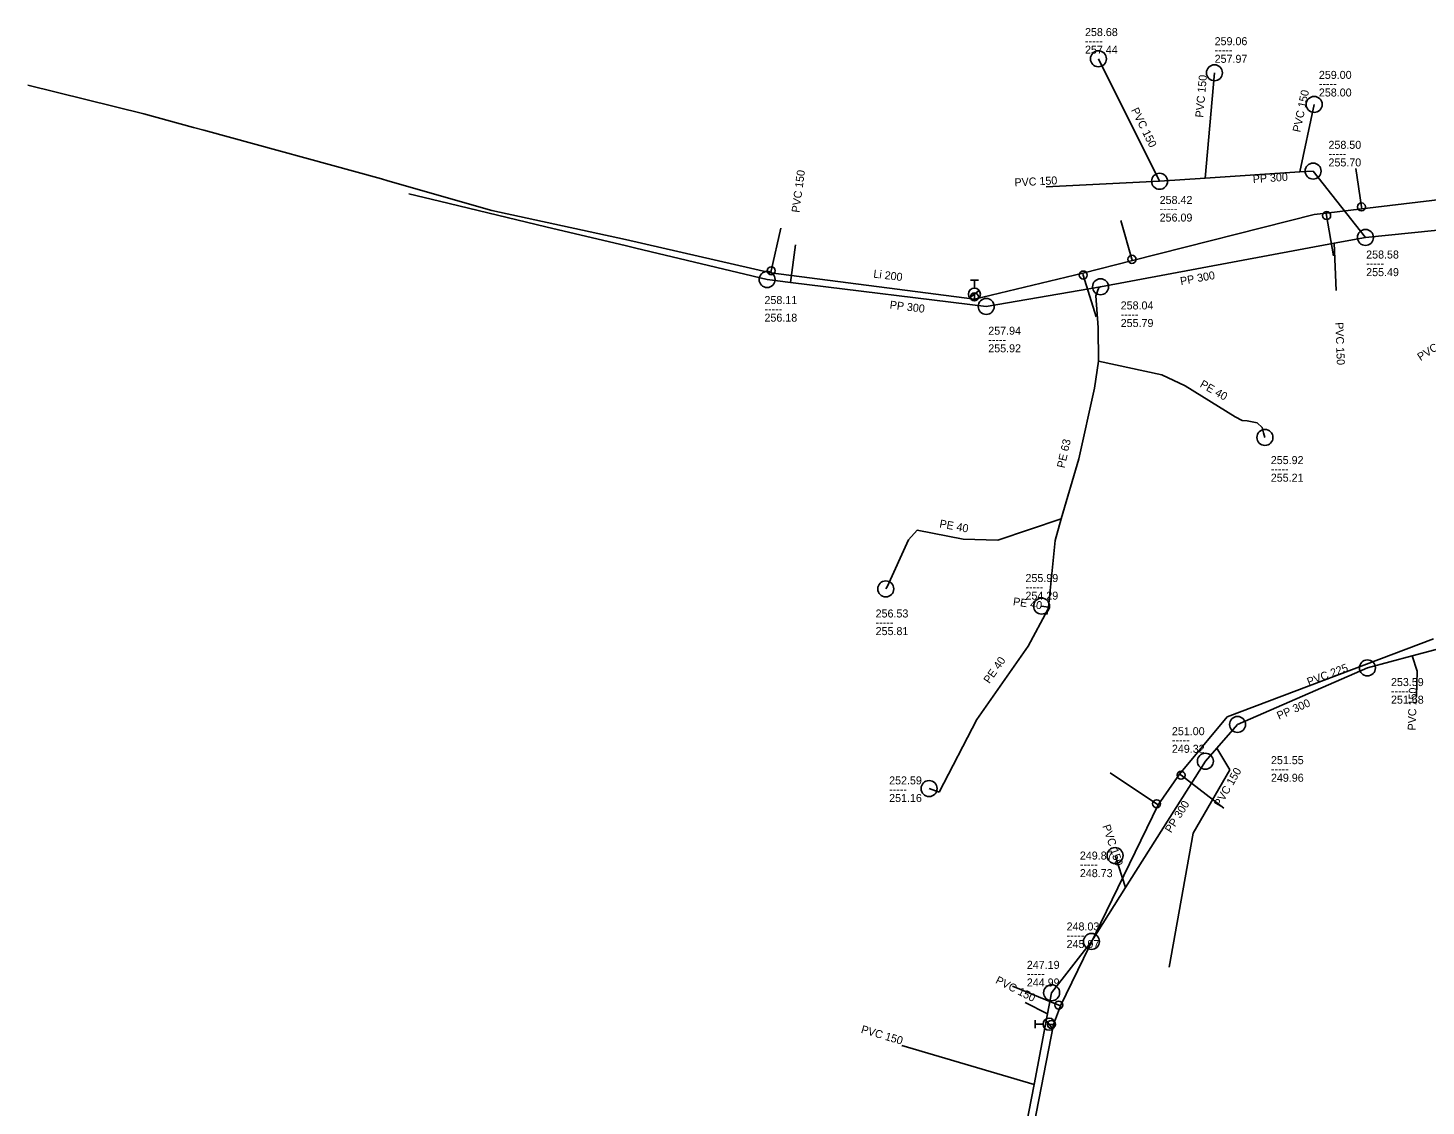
# Model space of a CAD drawing. Extents: x -770828 to -770111, y -1050344 to -1049447.
# Drawn here: x -770827.7 to -770653, y -1050061.2 to -1049926.5 of the extents above; entities that cross this region are included whole.
import ezdxf

# ---------------------------------------------------------------- set-up
doc = ezdxf.new("R2010")
doc.units = 0
doc.layers.add('Level 0', color=7, linetype='Continuous')

msp = doc.modelspace()

# ---------------------------------------------------------------- linework, layer by layer
at = {"layer": 'Level 0'}
for p, q in [((-770686.27, -1049945.68), (-770693.92, -1049930.37)), ((-770680.57, -1049945.3), (-770679.41, -1049932.12)), ((-770827.7, -1049933.66), (-770813.22, -1049937.25)), ((-770813.22, -1049937.25), (-770807.01, -1049938.95)), ((-770668.75, -1049944.51), (-770666.95, -1049936.07)), ((-770807.01, -1049938.95), (-770805.73, -1049939.3)), ((-770805.73, -1049939.3), (-770783.52, -1049945.37)), ((-770680.57, -1049945.3), (-770668.75, -1049944.51)), ((-770668.75, -1049944.51), (-770667.08, -1049944.4)), ((-770667.08, -1049944.4), (-770660.54, -1049952.69)), ((-770661.04, -1049948.87), (-770661.73, -1049944.09)), ((-770783.52, -1049945.37), (-770782.73, -1049945.6)), ((-770782.73, -1049945.6), (-770769.73, -1049949.34)), ((-770700.43, -1049946.39), (-770686.27, -1049945.68)), ((-770686.27, -1049945.68), (-770680.57, -1049945.3)), ((-770780.08, -1049947.26), (-770776.28, -1049948.17)), ((-770661, -1049949.12), (-770650.48, -1049947.87)), ((-770776.28, -1049948.17), (-770762.96, -1049951.35)), ((-770769.73, -1049949.34), (-770753.04, -1049952.96)), ((-770689.67, -1049955.59), (-770666.94, -1049949.83)), ((-770666.94, -1049949.83), (-770665.44, -1049949.65)), ((-770665.44, -1049949.65), (-770661, -1049949.12)), ((-770665.44, -1049949.65), (-770665.39, -1049949.97)), ((-770661, -1049949.12), (-770661.04, -1049948.87)), ((-770762.96, -1049951.35), (-770752.89, -1049953.75)), ((-770734.8, -1049956.86), (-770733.62, -1049951.55)), ((-770689.72, -1049955.43), (-770691.12, -1049950.59)), ((-770665.39, -1049949.97), (-770664.55, -1049955.01)), ((-770660.54, -1049952.69), (-770648.08, -1049951.45)), ((-770753.04, -1049952.96), (-770734.86, -1049957.12)), ((-770664.43, -1049953.41), (-770660.54, -1049952.69)), ((-770752.89, -1049953.75), (-770751.73, -1049954.03)), ((-770751.73, -1049954.03), (-770735.32, -1049957.95)), ((-770732.39, -1049958.31), (-770731.76, -1049953.63)), ((-770693.65, -1049958.86), (-770664.43, -1049953.41)), ((-770664.21, -1049959.33), (-770664.43, -1049953.41)), ((-770695.88, -1049957.16), (-770689.67, -1049955.59)), ((-770689.67, -1049955.59), (-770689.72, -1049955.43)), ((-770735.32, -1049957.95), (-770732.39, -1049958.31)), ((-770734.86, -1049957.12), (-770734.8, -1049956.86)), ((-770734.86, -1049957.12), (-770709.39, -1049960.4)), ((-770732.39, -1049958.31), (-770707.93, -1049961.32)), ((-770709.92, -1049958.02), (-770708.92, -1049958.02)), ((-770709.42, -1049959.02), (-770709.42, -1049958.02)), ((-770709.39, -1049960.4), (-770695.88, -1049957.16)), ((-770695.88, -1049957.16), (-770695.81, -1049957.39)), ((-770695.81, -1049957.39), (-770694.21, -1049962.61)), ((-770710.01, -1049960.23), (-770708.83, -1049959.31)), ((-770709.42, -1049959.77), (-770709.42, -1049960.13)), ((-770709.42, -1049960.13), (-770709.39, -1049960.4)), ((-770707.93, -1049961.32), (-770693.65, -1049958.86)), ((-770694.22, -1049959.98), (-770693.86, -1049958.95)), ((-770693.94, -1049963.95), (-770694.22, -1049959.98)), ((-770693.86, -1049958.95), (-770693.65, -1049958.86)), ((-770693.92, -1049968.17), (-770693.94, -1049963.95)), ((-770694.4, -1049971.53), (-770693.92, -1049968.17)), ((-770693.92, -1049968.17), (-770686, -1049969.86)), ((-770686, -1049969.86), (-770683.06, -1049971.22)), ((-770696.37, -1049980.37), (-770694.4, -1049971.53)), ((-770683.06, -1049971.22), (-770676.81, -1049975.12)), ((-770676.81, -1049975.12), (-770675.95, -1049975.56)), ((-770675.95, -1049975.56), (-770675.34, -1049975.63)), ((-770675.34, -1049975.63), (-770674.07, -1049975.87)), ((-770674.07, -1049975.87), (-770673.46, -1049976.46)), ((-770673.46, -1049976.46), (-770673.29, -1049977.12)), ((-770673.29, -1049977.12), (-770673.1, -1049977.69)), ((-770698.56, -1049987.85), (-770696.37, -1049980.37)), ((-770698.56, -1049987.85), (-770706.48, -1049990.52)), ((-770699.3, -1049990.55), (-770698.56, -1049987.85)), ((-770716.55, -1049989.29), (-770717.66, -1049990.48)), ((-770710.81, -1049990.4), (-770716.55, -1049989.29)), ((-770717.66, -1049990.48), (-770720.33, -1049996.37)), ((-770706.48, -1049990.52), (-770710.81, -1049990.4)), ((-770700.15, -1049998.9), (-770699.3, -1049990.55)), ((-770720.33, -1049996.37), (-770720.49, -1049996.62)), ((-770700.25, -1049999.18), (-770702.71, -1050003.76)), ((-770701.02, -1049998.77), (-770700.15, -1049998.9)), ((-770700.35, -1049999.81), (-770700.25, -1049999.18)), ((-770700.25, -1049999.18), (-770700.15, -1049998.9)), ((-770642.7, -1050001.79), (-770654.72, -1050005)), ((-770702.71, -1050003.76), (-770709.12, -1050012.92)), ((-770677.84, -1050012.6), (-770652.02, -1050002.86)), ((-770654.72, -1050005), (-770660.3, -1050006.49)), ((-770654.72, -1050005), (-770654.07, -1050006.89)), ((-770660.3, -1050006.49), (-770676.53, -1050013.56)), ((-770654.07, -1050006.89), (-770654.16, -1050010.06)), ((-770683.78, -1050019.75), (-770677.84, -1050012.6)), ((-770709.12, -1050012.92), (-770713.8, -1050022)), ((-770676.53, -1050013.56), (-770679.12, -1050016.52)), ((-770679.12, -1050016.52), (-770680.55, -1050018.15)), ((-770679.12, -1050016.52), (-770677.48, -1050019.23)), ((-770686.64, -1050023.47), (-770692.43, -1050019.6)), ((-770680.55, -1050018.15), (-770690.52, -1050033.93)), ((-770677.48, -1050019.23), (-770682.09, -1050027.16)), ((-770686.45, -1050023.6), (-770683.78, -1050019.75)), ((-770683.78, -1050019.75), (-770683.59, -1050019.9)), ((-770683.59, -1050019.9), (-770678.25, -1050024)), ((-770713.8, -1050022), (-770715.08, -1050021.57)), ((-770698.66, -1050048.72), (-770686.45, -1050023.6)), ((-770686.45, -1050023.6), (-770686.64, -1050023.47)), ((-770682.09, -1050027.16), (-770685.08, -1050043.91)), ((-770690.52, -1050033.93), (-770691.84, -1050029.94)), ((-770690.52, -1050033.93), (-770694.79, -1050040.68)), ((-770694.79, -1050040.68), (-770699.76, -1050047.09)), ((-770698.88, -1050048.63), (-770704.64, -1050046.25)), ((-770699.76, -1050047.09), (-770700.26, -1050049.71)), ((-770700.26, -1050049.71), (-770703.05, -1050048.29)), ((-770699.54, -1050051.07), (-770698.66, -1050048.72)), ((-770698.66, -1050048.72), (-770698.88, -1050048.63)), ((-770702.51, -1050066.39), (-770699.54, -1050051.07)), ((-770700.26, -1050049.71), (-770701.96, -1050058.56)), ((-770701.84, -1050051.51), (-770701.84, -1050050.51)), ((-770700.84, -1050051.01), (-770701.84, -1050051.01)), ((-770699.63, -1050051.6), (-770700.55, -1050050.42)), ((-770699.79, -1050051.05), (-770700.09, -1050051.01)), ((-770699.54, -1050051.07), (-770699.79, -1050051.05)), ((-770701.96, -1050058.56), (-770718.5, -1050053.69)), ((-770701.96, -1050058.56), (-770703.34, -1050065.74))]:
    msp.add_line(p, q, dxfattribs=at)
for centre, radius in [((-770693.92, -1049930.37), 1), ((-770679.41, -1049932.12), 1), ((-770666.95, -1049936.07), 1), ((-770667.08, -1049944.4), 1), ((-770686.27, -1049945.68), 1), ((-770665.39, -1049949.97), 0.5), ((-770661.04, -1049948.87), 0.5), ((-770660.54, -1049952.69), 1), ((-770689.72, -1049955.43), 0.5), ((-770734.8, -1049956.86), 0.5), ((-770735.32, -1049957.95), 1), ((-770695.81, -1049957.39), 0.5), ((-770693.65, -1049958.86), 1), ((-770709.42, -1049959.77), 0.75), ((-770709.42, -1049960.13), 0.5), ((-770707.93, -1049961.32), 1), ((-770673.1, -1049977.69), 1), ((-770720.49, -1049996.62), 1), ((-770701.02, -1049998.77), 1), ((-770660.3, -1050006.49), 1), ((-770676.53, -1050013.56), 1), ((-770680.55, -1050018.15), 1), ((-770683.59, -1050019.9), 0.5), ((-770715.08, -1050021.57), 1), ((-770686.64, -1050023.47), 0.5), ((-770691.84, -1050029.94), 1), ((-770694.79, -1050040.68), 1), ((-770699.76, -1050047.09), 1), ((-770698.88, -1050048.63), 0.5), ((-770700.09, -1050051.01), 0.75), ((-770699.79, -1050051.05), 0.5)]:
    msp.add_circle(centre, radius, dxfattribs=at)

# ---------------------------------------------------------------- texts
for s, p in [('258.68', (-770695.59, -1049927.53)), ('-----', (-770695.59, -1049928.63)), ('257.44', (-770695.59, -1049929.73)), ('259.06', (-770679.39, -1049928.67)), ('-----', (-770679.39, -1049929.77)), ('257.97', (-770679.39, -1049930.87)), ('259.00', (-770666.36, -1049932.88)), ('-----', (-770666.36, -1049933.98)), ('258.00', (-770666.36, -1049935.08)), ('258.50', (-770665.16, -1049941.62)), ('-----', (-770665.16, -1049942.72)), ('255.70', (-770665.16, -1049943.82)), ('258.42', (-770686.26, -1049948.51)), ('-----', (-770686.26, -1049949.61)), ('256.09', (-770686.26, -1049950.71)), ('258.58', (-770660.45, -1049955.33)), ('-----', (-770660.45, -1049956.43)), ('255.49', (-770660.45, -1049957.53)), ('258.11', (-770735.65, -1049961.02)), ('-----', (-770735.65, -1049962.12)), ('258.04', (-770691.13, -1049961.69)), ('256.18', (-770735.65, -1049963.22)), ('-----', (-770691.13, -1049962.79)), ('255.79', (-770691.13, -1049963.89)), ('-----', (-770707.68, -1049965.95)), ('257.94', (-770707.68, -1049964.85)), ('255.92', (-770707.68, -1049967.05)), ('255.92', (-770672.37, -1049981.02)), ('-----', (-770672.37, -1049982.12)), ('255.21', (-770672.37, -1049983.22)), ('255.99', (-770703.03, -1049995.76)), ('-----', (-770703.03, -1049996.86)), ('254.29', (-770703.03, -1049997.96)), ('256.53', (-770721.76, -1050000.19)), ('-----', (-770721.76, -1050001.29)), ('255.81', (-770721.76, -1050002.39)), ('253.59', (-770657.35, -1050008.76)), ('-----', (-770657.35, -1050009.86)), ('251.68', (-770657.35, -1050010.96)), ('251.00', (-770684.73, -1050014.9)), ('-----', (-770684.73, -1050016)), ('249.32', (-770684.73, -1050017.1)), ('251.55', (-770672.35, -1050018.52)), ('-----', (-770672.35, -1050019.62)), ('249.96', (-770672.35, -1050020.72)), ('252.59', (-770720.07, -1050021.05)), ('-----', (-770720.07, -1050022.15)), ('251.16', (-770720.07, -1050023.25)), ('249.87', (-770696.23, -1050030.44)), ('-----', (-770696.23, -1050031.54)), ('248.73', (-770696.23, -1050032.64)), ('248.03', (-770697.89, -1050039.3)), ('-----', (-770697.89, -1050040.4)), ('245.97', (-770697.89, -1050041.5)), ('247.19', (-770702.86, -1050044.1)), ('-----', (-770702.86, -1050045.2)), ('244.99', (-770702.86, -1050046.3))]:
    msp.add_text(s, height=1, dxfattribs=at).set_placement(p)
for s, rotation, p in [('PVC 150', 84.97, (-770680.82, -1049937.75)), ('PVC 150', 77.961, (-770668.69, -1049939.61)), ('PVC 150', 296.55, (-770689.86, -1049936.77)), ('PVC 150', 82.333, (-770731.29, -1049949.64)), ('PVC 150', 2.87, (-770704.38, -1049946.32)), ('PP 300', 3.824, (-770674.59, -1049945.9)), ('Li 200', 352.985, (-770722.08, -1049957.71)), ('PP 300', 10.486, (-770683.6, -1049958.67)), ('PP 300', 352.985, (-770720.04, -1049961.58)), ('PVC 150', 272.128, (-770664.31, -1049963.31)), ('PVC 150', 32.587, (-770653.66, -1049968.16)), ('PE 40', 330.484, (-770681.32, -1049971.32)), ('PE 63', 77.437, (-770698.15, -1049981.58)), ('PE 40', 349.477, (-770713.84, -1049988.92)), ('PE 40', 351.501, (-770704.64, -1049998.65)), ('PE 40', 55.175, (-770707.54, -1050008.53)), ('PVC 225', 20.668, (-770667.62, -1050008.74)), ('PVC 150', 88.374, (-770654.26, -1050014.32)), ('PP 300', 23.539, (-770671.35, -1050012.98)), ('PVC 150', 59.829, (-770678.68, -1050023.96)), ('PP 300', 57.715, (-770684.83, -1050027.19)), ('PVC 150', 288.306, (-770693.43, -1050026.25)), ('PVC 150', 333.026, (-770706.87, -1050045.84)), ('PVC 150', 343.594, (-770723.66, -1050052.08))]:
    msp.add_text(s, height=1, rotation=rotation, dxfattribs=at).set_placement(p)

doc.saveas('drawing.dxf')
